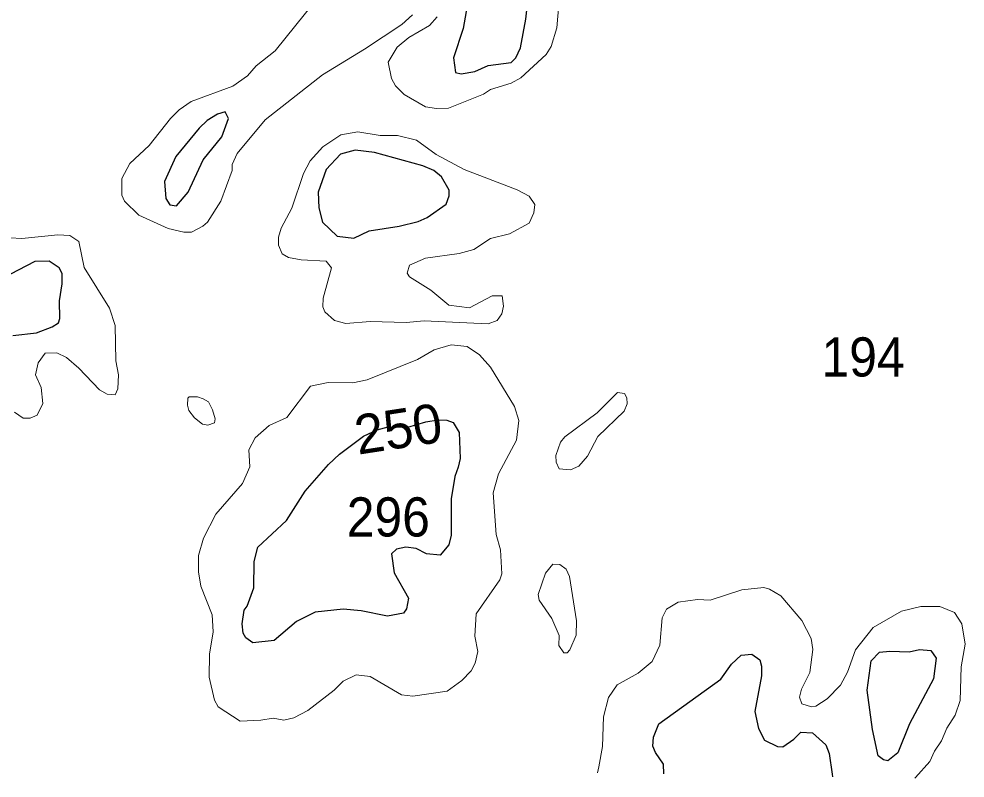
# Model space of a CAD drawing. Extents: x 763.2 to 816.8, y 7896.5 to 7952.7.
# Drawn here: x 807.081 to 810.942, y 7896.558 to 7899.656 of the extents above; entities that cross this region are included whole.
import ezdxf
from ezdxf.enums import TextEntityAlignment as Align

# ---------------------------------------------------------------- set-up
doc = ezdxf.new("R2010")
doc.units = 0
doc.header["$LTSCALE"] = 0.064
doc.layers.add('1', color=7, linetype='Continuous', lineweight=25)
doc.layers.add('2', color=7, linetype='Continuous', lineweight=13)
doc.layers.add('21', color=7, linetype='Continuous')
doc.layers.add('61', color=7, linetype='Continuous')

msp = doc.modelspace()

# ---------------------------------------------------------------- linework, layer by layer
at = {"layer": '1'}
for points in [[(808.9134, 7899.7342), (808.894, 7899.6176), (808.8543, 7899.4969), (808.8619, 7899.4368), (808.8856, 7899.4319), (808.9409, 7899.4412), (808.9958, 7899.4662), (809.0889, 7899.4788), (809.1077, 7899.4967), (809.1272, 7899.5378), (809.1485, 7899.6553), (809.1665, 7899.8131)], [(807.0551, 7898.3644), (807.1517, 7898.3752), (807.2161, 7898.4002), (807.2416, 7898.4165), (807.2469, 7898.4335), (807.2455, 7898.5057), (807.2568, 7898.5747), (807.2568, 7898.617), (807.2447, 7898.64), (807.2042, 7898.667), (807.1452, 7898.6657), (807.0119, 7898.5972)], [(809.7125, 7896.5752), (809.7103, 7896.6144), (809.6778, 7896.6628), (809.6679, 7896.6889), (809.67, 7896.7251), (809.6924, 7896.7801), (809.9449, 7896.9614), (809.9889, 7897.023), (810.0284, 7897.0593), (810.0712, 7897.0637), (810.1044, 7897.0408), (810.1112, 7897.0142), (810.1112, 7896.9748), (810.0838, 7896.8302), (810.0984, 7896.7603), (810.1227, 7896.713), (810.1758, 7896.6868), (810.1979, 7896.6858), (810.2429, 7896.7169), (810.2709, 7896.746), (810.3191, 7896.7425), (810.3734, 7896.6938), (810.3866, 7896.6579), (810.3993, 7896.5739), (810.4008, 7896.5637)]]:
    msp.add_lwpolyline(points, dxfattribs=at)
for points in [[(807.8327, 7899.0806), (807.9088, 7899.1748), (807.9364, 7899.2497), (807.9227, 7899.277), (807.8915, 7899.2672), (807.8486, 7899.241), (807.8162, 7899.2105), (807.7215, 7899.0948), (807.6745, 7898.9923), (807.6794, 7898.9232), (807.696, 7898.898), (807.7231, 7898.8939), (807.7717, 7898.9487)], [(808.6316, 7898.8107), (808.7104, 7898.829), (808.7465, 7898.8456), (808.8236, 7898.9001), (808.8361, 7898.934), (808.8361, 7898.9577), (808.8051, 7899.0122), (808.7731, 7899.0376), (808.7294, 7899.057), (808.5315, 7899.1115), (808.4533, 7899.1211), (808.3927, 7899.1046), (808.3348, 7899.0415), (808.3023, 7898.9486), (808.3039, 7898.8855), (808.3187, 7898.8272), (808.3788, 7898.7702), (808.4466, 7898.7618), (808.5101, 7898.791)], [(808.4868, 7897.9533), (808.5427, 7897.9796), (808.5869, 7897.9909), (808.667, 7897.9897), (808.7415, 7898.0124), (808.7907, 7898.02), (808.8261, 7898.0193), (808.8529, 7898.0097), (808.8775, 7897.969), (808.8806, 7897.8625), (808.8723, 7897.8271), (808.8587, 7897.7882), (808.8447, 7897.698), (808.8443, 7897.5492), (808.8346, 7897.5101), (808.7993, 7897.4681), (808.7442, 7897.4734), (808.7013, 7897.4956), (808.6589, 7897.5005), (808.6211, 7897.4923), (808.6003, 7897.4733), (808.6114, 7897.395), (808.6699, 7897.2924), (808.6623, 7897.2489), (808.6499, 7897.2313), (808.5848, 7897.2183), (808.4771, 7897.241), (808.404, 7897.2476), (808.2898, 7897.2346), (808.2133, 7897.1977), (808.1219, 7897.1201), (808.0344, 7897.1105), (808.0069, 7897.1306), (807.9956, 7897.1497), (807.9916, 7897.1869), (807.9997, 7897.2437), (808.0116, 7897.2603), (808.0389, 7897.3348), (808.0409, 7897.4425), (808.0552, 7897.501), (808.1728, 7897.6095), (808.248, 7897.7292), (808.3438, 7897.8382), (808.3893, 7897.8805)], [(810.5638, 7896.7567), (810.5423, 7896.9166), (810.5577, 7897.0361), (810.5918, 7897.0719), (810.6351, 7897.0766), (810.713, 7897.0734), (810.7549, 7897.0832), (810.8017, 7897.0781), (810.8229, 7897.0479), (810.8129, 7896.9628), (810.7147, 7896.7793), (810.6673, 7896.6617), (810.6259, 7896.6283), (810.609, 7896.6319), (810.5874, 7896.6488)]]:
    msp.add_lwpolyline(points, close=True, dxfattribs=at)
at = {"layer": '2'}
for points in [[(809.2869, 7899.7478), (809.275, 7899.6201), (809.252, 7899.5434), (809.2318, 7899.5103), (809.1288, 7899.4152), (809.0894, 7899.3944), (809.0045, 7899.3677), (808.9763, 7899.3486), (808.8333, 7899.292), (808.7847, 7899.2905), (808.7403, 7899.2973), (808.6527, 7899.3476), (808.6177, 7899.3826), (808.6008, 7899.4128), (808.5867, 7899.4794), (808.6235, 7899.5412), (808.672, 7899.5796), (808.7562, 7899.6295), (808.7877, 7899.664)], [(808.686, 7899.6729), (808.6429, 7899.6328), (808.4911, 7899.5321), (808.3187, 7899.4284), (808.0853, 7899.2444), (807.9711, 7899.1063), (807.951, 7899.0617), (807.9502, 7899.0374), (807.9041, 7898.9119), (807.8494, 7898.8266), (807.8309, 7898.8097), (807.7847, 7898.786), (807.7532, 7898.786), (807.6889, 7898.8003), (807.5692, 7898.855), (807.5111, 7898.9126), (807.5006, 7898.9364), (807.4999, 7899.0051), (807.5332, 7899.0667), (807.6124, 7899.1397), (807.6995, 7899.2498), (807.734, 7899.2845), (807.7829, 7899.3184), (807.9531, 7899.3823), (808.0128, 7899.4237), (808.0491, 7899.4647), (808.1266, 7899.5259), (808.2895, 7899.7281)], [(807.0619, 7898.0509), (807.0978, 7898.0272), (807.127, 7898.0268), (807.1553, 7898.0391), (807.1775, 7898.0861), (807.1714, 7898.1524), (807.1485, 7898.2032), (807.159, 7898.2532), (807.1881, 7898.2926), (807.2351, 7898.2933), (807.2745, 7898.2744), (807.3249, 7898.2314), (807.4094, 7898.1424), (807.4401, 7898.1241), (807.4735, 7898.1224), (807.4836, 7898.1467), (807.4871, 7898.2031), (807.4757, 7898.2611), (807.4735, 7898.405), (807.4506, 7898.4753), (807.3462, 7898.6423), (807.3256, 7898.748), (807.2886, 7898.7725), (807.2392, 7898.7743), (807.092, 7898.7597), (807.0446, 7898.7628)], [(809.4421, 7896.5797), (809.4466, 7896.6037), (809.4623, 7896.6866), (809.4661, 7896.8079), (809.4865, 7896.8863), (809.5219, 7896.9386), (809.6076, 7896.9868), (809.6652, 7897.0341), (809.6963, 7897.1006), (809.7056, 7897.2124), (809.7227, 7897.248), (809.7706, 7897.2762), (809.8495, 7897.2871), (809.9017, 7897.2841), (810.0311, 7897.3265), (810.1197, 7897.3364), (810.1435, 7897.3294), (810.1898, 7897.3023), (810.2754, 7897.2005), (810.3136, 7897.1277), (810.3201, 7897.0832), (810.308, 7896.9883), (810.2743, 7896.9206), (810.2662, 7896.8881), (810.2751, 7896.8612), (810.3143, 7896.8484), (810.3324, 7896.8512), (810.3794, 7896.8812), (810.4331, 7896.9366), (810.4616, 7896.9897), (810.4945, 7897.0815), (810.5663, 7897.173), (810.6819, 7897.2393), (810.7614, 7897.2576), (810.8382, 7897.2578), (810.8979, 7897.2336), (810.9285, 7897.1872), (810.9415, 7897.104), (810.9251, 7897.0119), (810.9214, 7896.8743), (810.9012, 7896.8155), (810.8668, 7896.7615), (810.8459, 7896.7103), (810.8168, 7896.6675), (810.798, 7896.6252), (810.7394, 7896.5608), (810.7369, 7896.5581)]]:
    msp.add_lwpolyline(points, dxfattribs=at)
for points in [[(809.0527, 7898.5256), (809.0581, 7898.4845), (809.0511, 7898.452), (809.0327, 7898.4256), (808.9957, 7898.4113), (808.7344, 7898.4244), (808.6604, 7898.4178), (808.5132, 7898.421), (808.4146, 7898.4129), (808.3689, 7898.4251), (808.329, 7898.4607), (808.3204, 7898.4807), (808.3221, 7898.5161), (808.356, 7898.6401), (808.3346, 7898.6673), (808.2329, 7898.673), (808.1812, 7898.6822), (808.1544, 7898.6974), (808.1394, 7898.7324), (808.1396, 7898.7652), (808.1505, 7898.8027), (808.1939, 7898.8836), (808.2412, 7899.0254), (808.2696, 7899.077), (808.3209, 7899.1334), (808.3939, 7899.1824), (808.463, 7899.1952), (808.5546, 7899.1804), (808.6256, 7899.1801), (808.7025, 7899.1608), (808.7833, 7899.1024), (808.8981, 7899.0417), (809.1134, 7898.9586), (809.1627, 7898.9325), (809.1863, 7898.8984), (809.1824, 7898.8643), (809.163, 7898.8223), (809.0825, 7898.7796), (809.0055, 7898.7596), (808.9371, 7898.7156), (808.8773, 7898.6989), (808.74, 7898.6793), (808.6749, 7898.6518), (808.6642, 7898.619), (808.6738, 7898.6035), (808.7612, 7898.5488), (808.835, 7898.4886), (808.9197, 7898.477), (809.0112, 7898.5262)], [(809.0461, 7897.4899), (809.0285, 7897.5524), (809.0154, 7897.722), (809.0375, 7897.7996), (809.1109, 7897.937), (809.1205, 7898.0179), (809.1023, 7898.0743), (809.0054, 7898.2354), (808.9599, 7898.2857), (808.9102, 7898.3191), (808.8441, 7898.3256), (808.7748, 7898.3057), (808.7064, 7898.2667), (808.502, 7898.1827), (808.4435, 7898.1713), (808.3423, 7898.173), (808.2698, 7898.1568), (808.1732, 7898.0298), (808.1023, 7897.9974), (808.0442, 7897.9461), (808.0182, 7897.8975), (808.0225, 7897.828), (807.9935, 7897.7596), (807.8839, 7897.635), (807.8333, 7897.5371), (807.8138, 7897.467), (807.8129, 7897.3994), (807.8228, 7897.3417), (807.8696, 7897.2237), (807.8733, 7897.1555), (807.8586, 7897.0634), (807.8569, 7896.9699), (807.8789, 7896.8766), (807.8941, 7896.8493), (807.9839, 7896.791), (808.0681, 7896.7941), (808.1186, 7896.8024), (808.162, 7896.7942), (808.2028, 7896.8037), (808.26, 7896.8339), (808.3667, 7896.9164), (808.4041, 7896.9534), (808.4568, 7896.9796), (808.5139, 7896.9732), (808.6414, 7896.8976), (808.6874, 7896.8928), (808.8274, 7896.9126), (808.8883, 7896.9562), (808.926, 7896.9958), (808.9429, 7897.0266), (808.953, 7897.0741), (808.9416, 7897.1376), (808.9463, 7897.2289), (809.0429, 7897.367), (809.0515, 7897.3921)], [(809.55, 7898.0551), (809.5621, 7898.0857), (809.5609, 7898.1097), (809.5513, 7898.1271), (809.5238, 7898.1313), (809.4399, 7898.0486), (809.3083, 7897.9512), (809.2906, 7897.9287), (809.2719, 7897.8742), (809.2735, 7897.8476), (809.2847, 7897.8204), (809.3317, 7897.8161), (809.3651, 7897.8311), (809.4005, 7897.8718), (809.4427, 7897.9526)], [(807.8535, 7898.0935), (807.8327, 7898.1055), (807.8093, 7898.1137), (807.7753, 7898.1136), (807.7703, 7898.1081), (807.768, 7898.0803), (807.7735, 7898.0578), (807.7967, 7898.0281), (807.8292, 7898.0017), (807.8512, 7897.9988), (807.8781, 7898.0078), (807.8812, 7898.0243), (807.8705, 7898.0605)], [(809.3277, 7897.381), (809.3143, 7897.4102), (809.2874, 7897.4299), (809.2587, 7897.4315), (809.2292, 7897.3949), (809.1996, 7897.3078), (809.2034, 7897.284), (809.2549, 7897.2088), (809.2849, 7897.1402), (809.284, 7897.0992), (809.3043, 7897.0686), (809.3182, 7897.0692), (809.3293, 7897.0818), (809.3539, 7897.1415), (809.3554, 7897.2)]]:
    msp.add_lwpolyline(points, close=True, dxfattribs=at)

# ---------------------------------------------------------------- texts
at = {"layer": '21', "width": 0.95}
for s, p in [('194', (810.3557, 7898.1967)), ('296', (808.4184, 7897.5438))]:
    msp.add_text(s, height=0.16, dxfattribs=at).set_placement(p)
at = {"layer": '61'}
msp.add_text('250', height=0.16, rotation=8.738, dxfattribs=at).set_placement((808.6406, 7897.9047), align=Align.CENTER)

doc.saveas('drawing.dxf')
